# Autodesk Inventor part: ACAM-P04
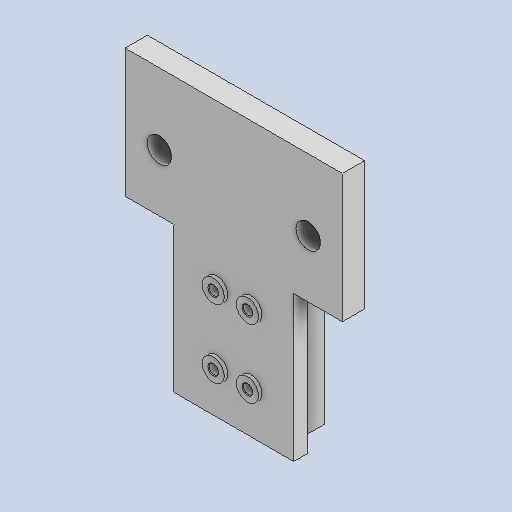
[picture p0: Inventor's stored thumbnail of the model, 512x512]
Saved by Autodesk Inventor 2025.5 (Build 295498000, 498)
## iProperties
Company: Open CASCADE
Created: 2026-10
Part Number: ACAM-P04
Material: Genérico
Description: Adaptador Jaco2–2040
Document SubType Name: Modeling
Designer: Luis M
Authority: Unknown
Density: 1 g/cm^3
Appearance: Valor por defecto
Sending System: Open CASCADE 7.9
Preprocessor: Open CASCADE STEP processor 7.9
Material_BOM: PLA
Proceso_BOM: Impresión 3D
Title: Open CASCADE Shape Model
Author: Author
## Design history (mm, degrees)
feature "Base1"
node "Sólido1"
